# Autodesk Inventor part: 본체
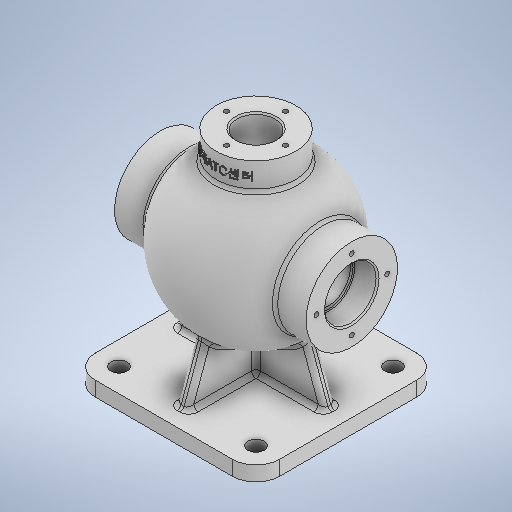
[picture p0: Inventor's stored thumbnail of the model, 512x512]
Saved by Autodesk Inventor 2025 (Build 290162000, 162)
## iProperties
Created: 2024-07
Part Number: 본체
Material: 일반
Document SubType Name: Modeling
Designer: song
Density: 1 g/cm^3
Appearance: 기본값
Author: song
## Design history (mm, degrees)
sketch "스케치1"
  geometry: L1 (-62.5, 62.5)-(62.5, 62.5); L2 (62.5, 62.5)-(62.5, -62.5); L3 (62.5, -62.5)-(-62.5, -62.5); L4 (-62.5, -62.5)-(-62.5, 62.5); L5 (-62.5, 62.5)-(62.5, -62.5); L6 (62.5, 62.5)-(-62.5, -62.5); 1 further point
  constraints: 12 end point, 2 midpoint, 2 parallel, 1 horizontal, 1 perpendicular
  dimensions: "d0" = 125 distance of L2.end L3.end; "d1" = 125 distance of L3.end L1.start
extrude "돌출1" new body sketch "스케치1" distance "d2" = 10; taper "d3" = 0 deg
sketch "스케치2"
  geometry: L1 (-62.5, 0)-(62.5, 0) reference; L2 (-65, 85)-(117.341, 85); L3 (-65, 85)-(-65, 116); L4 (-65, 116)-(-44.215, 116); L5 (65, 85)-(65, 116); L6 (65, 116)-(44.215, 116); L7 (0, 154.371)-(0, -36.93); A1 r 54 centre (0, 85) between (44.215, 116) and (-44.215, 116); 2 further points
  constraints: 12 end point, 3 point on line, 3 vertical, 2 perpendicular, 2 point on circle, 1 centre point, 1 horizontal, 1 midpoint, 1 vertical alignment, 1 other
  dimensions: "d5" = 85 distance between parallel lines of L1 L2; "d6" = 31 distance between parallel lines of L2 L4; "d7" = 65 distance from line of A1.centre L3; "d8" = 31 distance between parallel lines of L2 L6; "d9" = 54 radius of A1
revolve "회전1" sketch "스케치2" stored, may be unused: angle "d10" = 90 deg
node "작업 평면1"
sketch "스케치3"
  geometry: C1 r 27 at (0, 0); 1 further point
  constraints: 1 centre point, 1 coincident
  dimensions: "d12" = 54 diameter of C1
extrude "돌출2" join sketch "스케치3" stored distance "d13" = 10; taper "d14" = 0 deg
sketch "스케치4"
  geometry: L1 (-32.301, 60)-(-50.5, 10); L2 (62.5, 10)-(-62.5, 10) reference; L3 (-62.5, 0)-(-62.5, 10) reference; L4 (-50.5, 10)-(50.5, 10); L5 (50.5, 10)-(32.301, 60); L6 (62.5, 0)-(62.5, 10) reference; L7 (-32.301, 60)-(32.301, 60); A1 r 54 centre (0, 85) between (-44.215, 54) and (-44.215, 116) reference; 1 further point
  constraints: 8 end point, 1 collinear, 1 point on line
  dimensions: "d15" = 12 distance of L2.end L1.end; "d16" = 20 deg angle of L1 L3; "d17" = 12 distance of L2.start L4.end; "d18" = 20 deg angle of L6 L5; "d67" = 50 distance between parallel lines of L2 L7
extrude "돌출3" join sketch "스케치4" stored distance "d19" = 8; taper "d20" = 0 deg
sketch "스케치5"
  geometry: L1 (60, 32.301)-(10, 50.5); L2 (10, -62.5)-(10, 62.5) reference; L3 (10, -50.5)-(60, -32.301); L4 (0, -62.5)-(10, -62.5) reference; L5 (0, 62.5)-(10, 62.5) reference; L6 (60, 32.301)-(60, -32.301); L7 (10, 50.5)-(10, -50.5); A1 r 54 centre (85, 0) between (131.765, 27) and (131.765, -27) reference; 1 further point
  constraints: 8 end point, 2 point on line, 1 collinear, 1 vertical
  dimensions: "d21" = 12 distance of L2.end L1.end; "d22" = 12 distance of L2.start L3.start; "d23" = 20 deg angle of L4 L3; "d24" = 20 deg angle of L5 L1; "d68" = 50 distance between parallel lines of L2 L6
extrude "돌출4" join sketch "스케치5" stored distance "d25" = 8; taper "d26" = 0 deg
sketch "스케치6"
  geometry: L1 (-91.554, 85)-(140.899, 85); L2 (-65, 85)-(-65, 102.5); L3 (-65, 102.5)-(-49, 102.5); L4 (-49, 102.5)-(-49, 100); L5 (49, 100)-(49, 102.5); L6 (49, 102.5)-(65, 102.5); L7 (65, 102.5)-(65, 85); L8 (-65, 54)-(-65, 116) reference; L9 (65, 54)-(65, 116) reference; L10 (0, 180.652)-(0, -35.497); L11 (-49, 100)-(49, 100); A1 r 44 centre (0, 85) between (41.364, 100) and (-41.364, 100); A2 r 54 centre (0, 85) between (37.385, 46.034) and (-37.385, 46.034) reference; 1 further point
  constraints: 18 end point, 6 point on line, 4 perpendicular, 2 collinear, 2 horizontal, 2 point on circle, 2 vertical, 1 centre point, 1 concentric
  dimensions: "d27" = 44 radius of A1; "d28" = 17.5 distance of L2.start L2.end; "d29" = 16 distance between parallel lines of L4 L2; "d30" = 15 distance between parallel lines of L1 L11; "d31" = 16 distance between parallel lines of L9 L5; "d32" = 17.5 distance between parallel lines of L1 L6
revolve "회전2" stored, may be unused: angle "d33" = 90 deg
revolve "회전3" stored, may be unused: angle "d34" = 90 deg
sketch "스케치7"
  geometry: C1 r 27 at (0, 0) reference; 2 further points
  constraints: 1 coincident
hole "구멍1" sketch "스케치7" at (0, 0) diameter "d35" = 26; stored, may be unused: countersink angle "d39" = 90 deg, drill point angle "d41" = 0 deg; dims "d36" = 6, "d37" = 4, "d38" = 2, "d40" = 8
sketch "스케치8"
  geometry: C1 r 31 at (0, 0) reference; 2 further points
  constraints: 1 vertical alignment
  dimensions: "d49" = 24 distance of C1.centre point (0, 24)
hole "구멍2" sketch "스케치8" at (0, 24) diameter "d42" = 3.242; stored, may be unused: countersink angle "d46" = 90 deg, drill point angle "d48" = 120 deg; dims "d43" = 12, "d44" = 4, "d45" = 2, "d47" = 15
sketch "스케치9"
  geometry: 2 further points
  constraints: 1 vertical alignment
  dimensions: "d60" = 20 distance of point (0, -20) point (0, 0)
hole "구멍3" sketch "스케치9" at (0, -20) diameter "d53" = 3.242; stored, may be unused: countersink angle "d57" = 90 deg, drill point angle "d59" = 120 deg; dims "d54" = 9, "d55" = 4, "d56" = 2, "d58" = 11
fillet "모깎기1" dims "d65" = 3
fillet "모깎기3" dims "d69" = 3
fillet "모깎기4" dims "d70" = 3
fillet "모깎기5" dims "d79" = 16
sketch "스케치13"
  geometry: A1 r 16 centre (-46.5, 46.5) between (-46.5, 62.5) and (-62.5, 46.5) reference; A2 r 16 centre (46.5, 46.5) between (62.5, 46.5) and (46.5, 62.5) reference; A3 r 16 centre (-46.5, -46.5) between (-62.5, -46.5) and (-46.5, -62.5) reference; A4 r 16 centre (46.5, -46.5) between (46.5, -62.5) and (62.5, -46.5) reference; 5 further points
  constraints: 4 coincident
hole "구멍5" sketch "스케치13" at (-46.5, 46.5), (46.5, 46.5), (-46.5, -46.5), (46.5, -46.5) diameter "d80" = 11; stored, may be unused: countersink angle "d84" = 90 deg, drill point angle "d86" = 0 deg; dims "d81" = 6, "d82" = 4, "d83" = 2, "d85" = 8
node "작업 평면3"
sketch "스케치14"
  geometry: L1 (27, 150)-(-27, 150) reference; 2 further points
  constraints: 1 vertical alignment, 1 other
  dimensions: "d88" = 9 distance from line of point (0, 141) L1
feature "엠보싱1" sketch "스케치14" dims "d0" = 125, "d1" = 125, "d89" = 0.5, "d90" = 0
chamfer "모따기1" distance "d95" = 1; stored, may be unused: second distance "d96" = 2, angle "d97" = 45 deg
fillet "모깎기6" dims "d98" = 0.6
node "솔리드1"
pattern_circular "원형 패턴1" dims angle "d51" = 360 deg
mirror "미러1"
pattern_circular "원형 패턴2" dims angle "d62" = 360 deg
feature "A9D066F2-1C7D-4E18-AEED-F7BC21143FA4" dims "d80" = 11, "d81" = 6, "d82" = 4, "d83" = 2, "d84" = 90 deg, "d85" = 8, "d86" = 0
other parameters: "d4" = 54, "d87" = 27
